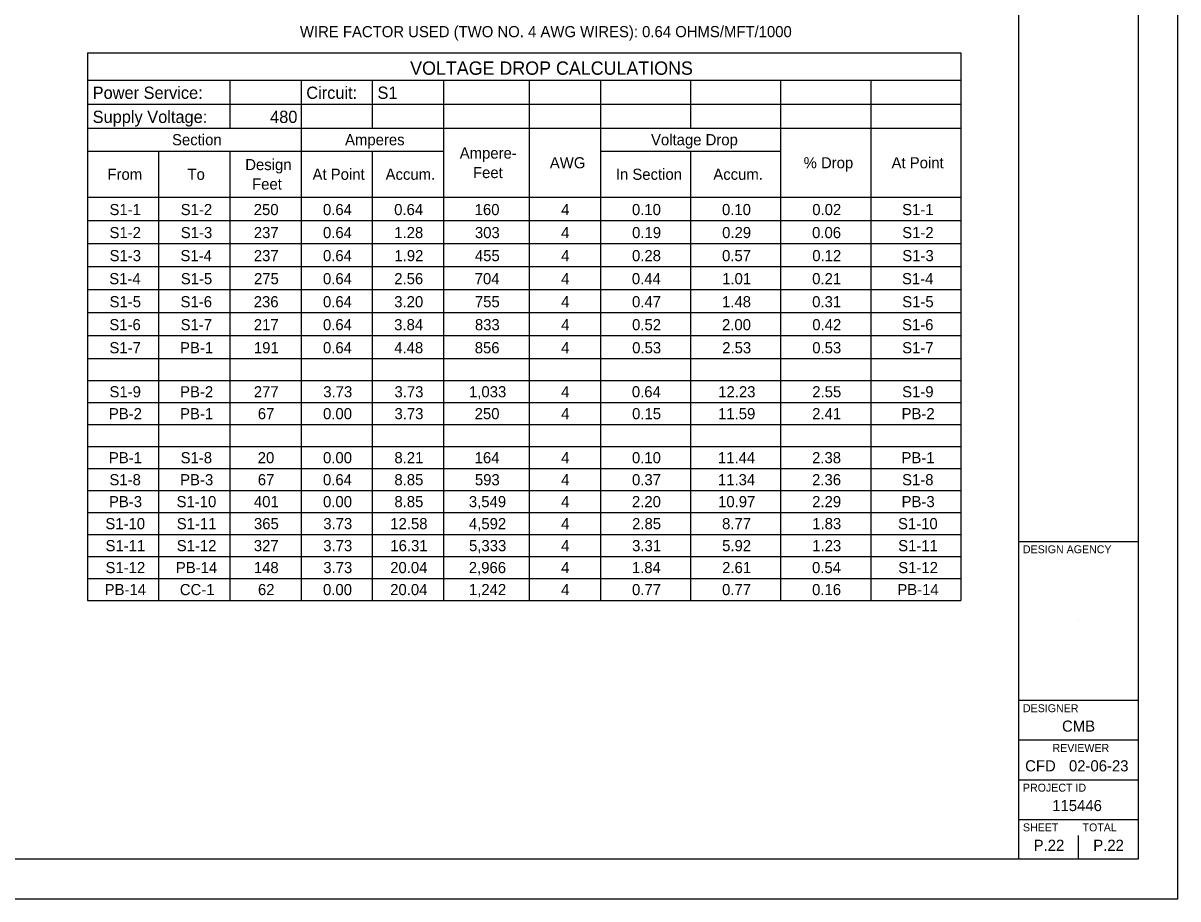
# Model space of a CAD drawing. Extents: x 0 to 34, y 0 to 22.
# Drawn here: x 19.47 to 34, y 0 to 11.02 of the extents above; entities that cross this region are included whole.
import ezdxf

# ---------------------------------------------------------------- set-up
doc = ezdxf.new("R2010")
doc.units = 0
for name, color, linetype in [('Default', 7, 'Continuous'), ('SH_Border', 7, 'Continuous'), ('SH_Cut_Line', 7, 'Continuous'), ('SH_Data', 7, 'Continuous'), ('SH_Text', 7, 'Continuous')]:
    doc.layers.add(name, color=color, linetype=linetype)

msp = doc.modelspace()

# ---------------------------------------------------------------- linework, layer by layer
at = {"layer": 'SH_Border'}
for p, q in [((32, 0.5), (32, 21.5)), ((32, 4.5), (33.5, 4.5)), ((32, 2.5), (33.5, 2.5)), ((32, 2), (33.5, 2)), ((32, 1.5), (33.5, 1.5)), ((32, 1), (33.5, 1))]:
    msp.add_line(p, q, dxfattribs=at)
msp.add_lwpolyline([(1.5, 21.5), (33.5, 21.5), (33.5, 0.5), (1.5, 0.5)], close=True, dxfattribs=at)
at = {"layer": 'SH_Cut_Line'}
msp.add_lwpolyline([(0, 0), (34, 0), (34, 22), (0, 22)], close=True, dxfattribs=at)
at = {"layer": 'SH_Data'}
for p, q in [((32.75, 3.5), (32.75, 3.5)), ((32.75, 0.5), (32.75, 0.8)), ((32.375, 0.675), (32.375, 0.675))]:
    msp.add_line(p, q, dxfattribs=at)
at = {"layer": 'SH_Text'}
for p, q in [((20.278, 10.648), (22.966, 10.648)), ((20.278, 10.648), (20.278, 9.7)), ((22.966, 10.648), (23.862, 10.648)), ((23.862, 10.648), (24.758, 10.648)), ((24.758, 10.648), (27.868, 10.648)), ((27.868, 10.648), (31.267, 10.648)), ((31.267, 10.648), (31.267, 9.7)), ((20.278, 10.306), (22.966, 10.306)), ((22.07, 10.306), (22.07, 9.7)), ((22.966, 10.306), (23.862, 10.306)), ((22.966, 10.306), (22.966, 9.7)), ((23.862, 10.306), (24.758, 10.306)), ((23.862, 10.306), (23.862, 9.7)), ((24.758, 10.306), (27.868, 10.306)), ((24.758, 10.306), (24.758, 9.7)), ((25.838, 10.306), (25.838, 9.7)), ((26.734, 10.306), (26.734, 9.7)), ((27.868, 10.306), (31.267, 10.306)), ((27.868, 10.306), (27.868, 9.7)), ((29.001, 10.306), (29.001, 9.7)), ((30.134, 10.306), (30.134, 9.7)), ((20.278, 10.003), (22.966, 10.003)), ((22.966, 10.003), (23.862, 10.003)), ((23.862, 10.003), (24.758, 10.003)), ((24.758, 10.003), (27.868, 10.003)), ((27.868, 10.003), (31.267, 10.003)), ((20.278, 9.7), (22.966, 9.7)), ((20.278, 9.7), (20.278, 7.381)), ((22.966, 9.7), (23.862, 9.7)), ((22.966, 9.7), (22.966, 7.381)), ((23.862, 9.7), (24.758, 9.7)), ((24.758, 9.7), (27.868, 9.7)), ((24.758, 9.7), (24.758, 7.381)), ((25.838, 9.7), (25.838, 7.381)), ((26.734, 9.7), (26.734, 7.381)), ((27.868, 9.7), (31.267, 9.7)), ((29.001, 9.7), (29.001, 7.381)), ((30.134, 9.7), (30.134, 7.381)), ((31.267, 9.7), (31.267, 7.381)), ((20.278, 9.41), (22.966, 9.41)), ((21.174, 9.41), (21.174, 7.381)), ((22.07, 9.41), (22.07, 7.381)), ((22.966, 9.41), (23.862, 9.41)), ((23.862, 9.41), (24.758, 9.41)), ((23.862, 9.41), (23.862, 7.381)), ((26.734, 9.41), (27.868, 9.41)), ((27.868, 9.41), (29.001, 9.41)), ((27.868, 9.41), (27.868, 7.381)), ((20.278, 8.83), (22.966, 8.83)), ((22.966, 8.83), (23.862, 8.83)), ((23.862, 8.83), (24.758, 8.83)), ((24.758, 8.83), (27.868, 8.83)), ((27.868, 8.83), (31.267, 8.83)), ((20.278, 8.54), (22.966, 8.54)), ((22.966, 8.54), (23.862, 8.54)), ((23.862, 8.54), (24.758, 8.54)), ((24.758, 8.54), (27.868, 8.54)), ((27.868, 8.54), (31.267, 8.54)), ((20.278, 8.25), (22.966, 8.25)), ((22.966, 8.25), (23.862, 8.25)), ((23.862, 8.25), (24.758, 8.25)), ((24.758, 8.25), (27.868, 8.25)), ((27.868, 8.25), (31.267, 8.25)), ((20.278, 7.96), (22.966, 7.96)), ((22.966, 7.96), (23.862, 7.96)), ((23.862, 7.96), (24.758, 7.96)), ((24.758, 7.96), (27.868, 7.96)), ((27.868, 7.96), (31.267, 7.96)), ((20.278, 7.67), (22.966, 7.67)), ((22.966, 7.67), (23.862, 7.67)), ((23.862, 7.67), (24.758, 7.67)), ((24.758, 7.67), (27.868, 7.67)), ((27.868, 7.67), (31.267, 7.67)), ((20.278, 7.381), (22.966, 7.381)), ((20.278, 7.381), (20.278, 7.091)), ((21.174, 7.381), (21.174, 7.091)), ((22.07, 7.381), (22.07, 7.091)), ((22.966, 7.381), (23.862, 7.381)), ((22.966, 7.381), (22.966, 7.091)), ((23.862, 7.381), (24.758, 7.381)), ((23.862, 7.381), (23.862, 7.091)), ((24.758, 7.381), (27.868, 7.381)), ((24.758, 7.381), (24.758, 7.091)), ((25.838, 7.381), (25.838, 7.091)), ((26.734, 7.381), (26.734, 7.091)), ((27.868, 7.381), (31.267, 7.381)), ((27.868, 7.381), (27.868, 7.091)), ((29.001, 7.381), (29.001, 7.091)), ((30.134, 7.381), (30.134, 7.091)), ((31.267, 7.381), (31.267, 7.091)), ((20.278, 7.091), (22.966, 7.091)), ((20.278, 7.091), (20.278, 4.864)), ((21.174, 7.091), (21.174, 4.864)), ((22.07, 7.091), (22.07, 4.864)), ((22.966, 7.091), (23.862, 7.091)), ((22.966, 7.091), (22.966, 4.864)), ((23.862, 7.091), (24.758, 7.091)), ((23.862, 7.091), (23.862, 4.864)), ((24.758, 7.091), (27.868, 7.091)), ((24.758, 7.091), (24.758, 4.864)), ((25.838, 7.091), (25.838, 4.864)), ((26.734, 7.091), (26.734, 4.864)), ((27.868, 7.091), (31.267, 7.091)), ((27.868, 7.091), (27.868, 4.864)), ((29.001, 7.091), (29.001, 4.864)), ((30.134, 7.091), (30.134, 4.864)), ((31.267, 7.091), (31.267, 4.864)), ((20.278, 6.801), (22.966, 6.801)), ((22.966, 6.801), (23.862, 6.801)), ((23.862, 6.801), (24.758, 6.801)), ((24.758, 6.801), (27.868, 6.801)), ((27.868, 6.801), (31.267, 6.801)), ((20.278, 6.524), (22.966, 6.524)), ((22.966, 6.524), (23.862, 6.524)), ((23.862, 6.524), (24.758, 6.524)), ((24.758, 6.524), (27.868, 6.524)), ((27.868, 6.524), (31.267, 6.524)), ((20.278, 6.247), (22.966, 6.247)), ((22.966, 6.247), (23.862, 6.247)), ((23.862, 6.247), (24.758, 6.247)), ((24.758, 6.247), (27.868, 6.247)), ((27.868, 6.247), (31.267, 6.247)), ((20.278, 5.971), (22.966, 5.971)), ((22.966, 5.971), (23.862, 5.971)), ((23.862, 5.971), (24.758, 5.971)), ((24.758, 5.971), (27.868, 5.971)), ((27.868, 5.971), (31.267, 5.971)), ((20.278, 5.694), (22.966, 5.694)), ((22.966, 5.694), (23.862, 5.694)), ((23.862, 5.694), (24.758, 5.694)), ((24.758, 5.694), (27.868, 5.694)), ((27.868, 5.694), (31.267, 5.694)), ((20.278, 5.417), (22.966, 5.417)), ((22.966, 5.417), (23.862, 5.417)), ((23.862, 5.417), (24.758, 5.417)), ((24.758, 5.417), (27.868, 5.417)), ((27.868, 5.417), (31.267, 5.417)), ((20.278, 5.141), (22.966, 5.141)), ((22.966, 5.141), (23.862, 5.141)), ((23.862, 5.141), (24.758, 5.141)), ((24.758, 5.141), (27.868, 5.141)), ((27.868, 5.141), (31.267, 5.141)), ((20.278, 4.864), (22.966, 4.864)), ((20.278, 4.864), (20.278, 4.587)), ((21.174, 4.864), (21.174, 4.587)), ((22.07, 4.864), (22.07, 4.587)), ((22.966, 4.864), (23.862, 4.864)), ((22.966, 4.864), (22.966, 4.587)), ((23.862, 4.864), (24.758, 4.864)), ((23.862, 4.864), (23.862, 4.587)), ((24.758, 4.864), (27.868, 4.864)), ((24.758, 4.864), (24.758, 4.587)), ((25.838, 4.864), (25.838, 4.587)), ((26.734, 4.864), (26.734, 4.587)), ((27.868, 4.864), (31.267, 4.864)), ((27.868, 4.864), (27.868, 4.587)), ((29.001, 4.864), (29.001, 4.587)), ((30.134, 4.864), (30.134, 4.587)), ((31.267, 4.864), (31.267, 4.587)), ((20.278, 4.587), (22.966, 4.587)), ((20.278, 4.587), (20.278, 4.31)), ((21.174, 4.587), (21.174, 4.31)), ((22.07, 4.587), (22.07, 4.31)), ((22.966, 4.587), (23.862, 4.587)), ((22.966, 4.587), (22.966, 4.31)), ((23.862, 4.587), (24.758, 4.587)), ((23.862, 4.587), (23.862, 4.31)), ((24.758, 4.587), (27.868, 4.587)), ((24.758, 4.587), (24.758, 4.31)), ((25.838, 4.587), (25.838, 4.31)), ((26.734, 4.587), (26.734, 4.31)), ((27.868, 4.587), (31.267, 4.587)), ((27.868, 4.587), (27.868, 4.31)), ((29.001, 4.587), (29.001, 4.31)), ((30.134, 4.587), (30.134, 4.31)), ((31.267, 4.587), (31.267, 4.31)), ((20.278, 4.31), (22.966, 4.31)), ((20.278, 4.31), (20.278, 4.034)), ((21.174, 4.31), (21.174, 4.034)), ((22.07, 4.31), (22.07, 4.034)), ((22.966, 4.31), (23.862, 4.31)), ((22.966, 4.31), (22.966, 4.034)), ((23.862, 4.31), (24.758, 4.31)), ((23.862, 4.31), (23.862, 4.034)), ((24.758, 4.31), (27.868, 4.31)), ((24.758, 4.31), (24.758, 4.034)), ((25.838, 4.31), (25.838, 4.034)), ((26.734, 4.31), (26.734, 4.034)), ((27.868, 4.31), (31.267, 4.31)), ((27.868, 4.31), (27.868, 4.034)), ((29.001, 4.31), (29.001, 4.034)), ((30.134, 4.31), (30.134, 4.034)), ((31.267, 4.31), (31.267, 4.034)), ((20.278, 4.034), (22.966, 4.034)), ((20.278, 4.034), (20.278, 3.757)), ((21.174, 4.034), (21.174, 3.757)), ((22.07, 4.034), (22.07, 3.757)), ((22.966, 4.034), (23.862, 4.034)), ((22.966, 4.034), (22.966, 3.757)), ((23.862, 4.034), (24.758, 4.034)), ((23.862, 4.034), (23.862, 3.757)), ((24.758, 4.034), (27.868, 4.034)), ((24.758, 4.034), (24.758, 3.757)), ((25.838, 4.034), (25.838, 3.757)), ((26.734, 4.034), (26.734, 3.757)), ((27.868, 4.034), (31.267, 4.034)), ((27.868, 4.034), (27.868, 3.757)), ((29.001, 4.034), (29.001, 3.757)), ((30.134, 4.034), (30.134, 3.757)), ((31.267, 4.034), (31.267, 3.757)), ((20.278, 3.757), (22.966, 3.757)), ((22.966, 3.757), (23.862, 3.757)), ((23.862, 3.757), (24.758, 3.757)), ((24.758, 3.757), (27.868, 3.757)), ((27.868, 3.757), (31.267, 3.757))]:
    msp.add_line(p, q, dxfattribs=at)

# ---------------------------------------------------------------- texts
at = {"layer": 'Default'}
msp.add_text('WIRE FACTOR USED (TWO NO. 4 AWG WIRES): 0.64 OHMS/MFT/1000', height=0.14, dxfattribs=at).set_placement((22.952, 10.845))
at = {"layer": 'SH_Data'}
for s, height, p in [('DESIGN AGENCY', 0.1, (32.05, 4.35)), ('DESIGNER', 0.1, (32.05, 2.35)), ('CMB', 0.14, (32.542, 2.105)), ('REVIEWER', 0.1, (32.422, 1.85)), ('CFD', 0.14, (32.078, 1.605)), ('02-06-23', 0.14, (32.629, 1.605)), ('PROJECT ID', 0.1, (32.05, 1.35)), ('115446', 0.14, (32.419, 1.105)), ('SHEET', 0.1, (32.05, 0.85)), ('TOTAL', 0.1, (32.8, 0.85)), ('P.22', 0.14, (32.185, 0.605)), ('P.22', 0.14, (32.935, 0.605))]:
    msp.add_text(s, height=height, dxfattribs=at).set_placement(p)
at = {"layer": 'SH_Text'}
for s, height, p in [('VOLTAGE DROP CALCULATIONS', 0.168, (24.339, 10.372)), ('Power Service:', 0.154, (20.344, 10.069)), ('Circuit:', 0.154, (23.032, 10.069)), ('S1', 0.154, (23.928, 10.069)), ('Supply Voltage:', 0.154, (20.344, 9.766)), ('480', 0.154, (22.577, 9.766)), ('Section', 0.14, (21.343, 9.485)), ('Amperes', 0.14, (23.52, 9.485)), ('Voltage Drop', 0.14, (27.37, 9.485)), ('Ampere-', 0.14, (24.963, 9.317)), ('Design', 0.14, (22.264, 9.172)), ('AWG', 0.14, (26.097, 9.195)), ('% Drop', 0.14, (29.29, 9.195)), ('At Point', 0.14, (30.397, 9.195)), ('From', 0.14, (20.53, 9.05)), ('To', 0.14, (21.537, 9.05)), ('At Point', 0.14, (23.111, 9.05)), ('Accum.', 0.14, (24.03, 9.05)), ('Feet', 0.14, (25.13, 9.072)), ('In Section', 0.14, (26.927, 9.05)), ('Accum.', 0.14, (28.154, 9.05)), ('Feet', 0.14, (22.35, 8.927)), ('S1-1', 0.14, (20.556, 8.606)), ('S1-2', 0.14, (21.452, 8.606)), ('250', 0.14, (22.371, 8.606)), ('0.64', 0.14, (23.242, 8.606)), ('0.64', 0.14, (24.138, 8.606)), ('160', 0.14, (25.151, 8.606)), ('4', 0.14, (26.239, 8.606)), ('0.10', 0.14, (27.13, 8.606)), ('0.10', 0.14, (28.263, 8.606)), ('0.02', 0.14, (29.399, 8.606)), ('S1-1', 0.14, (30.53, 8.606)), ('S1-2', 0.14, (20.556, 8.316)), ('S1-3', 0.14, (21.453, 8.316)), ('237', 0.14, (22.372, 8.316)), ('0.64', 0.14, (23.242, 8.316)), ('1.28', 0.14, (24.139, 8.316)), ('303', 0.14, (25.154, 8.316)), ('4', 0.14, (26.239, 8.316)), ('0.19', 0.14, (27.132, 8.316)), ('0.29', 0.14, (28.265, 8.316)), ('0.06', 0.14, (29.397, 8.316)), ('S1-2', 0.14, (30.531, 8.316)), ('S1-3', 0.14, (20.557, 8.026)), ('S1-4', 0.14, (21.449, 8.026)), ('237', 0.14, (22.372, 8.026)), ('0.64', 0.14, (23.242, 8.026)), ('1.92', 0.14, (24.141, 8.026)), ('455', 0.14, (25.154, 8.026)), ('4', 0.14, (26.239, 8.026)), ('0.28', 0.14, (27.131, 8.026)), ('0.57', 0.14, (28.264, 8.026)), ('0.12', 0.14, (29.399, 8.026)), ('S1-3', 0.14, (30.532, 8.026)), ('S1-4', 0.14, (20.553, 7.736)), ('S1-5', 0.14, (21.453, 7.736)), ('275', 0.14, (22.374, 7.736)), ('0.64', 0.14, (23.242, 7.736)), ('2.56', 0.14, (24.139, 7.736)), ('704', 0.14, (25.151, 7.736)), ('4', 0.14, (26.239, 7.736)), ('0.44', 0.14, (27.129, 7.736)), ('1.01', 0.14, (28.265, 7.736)), ('0.21', 0.14, (29.398, 7.736)), ('S1-4', 0.14, (30.528, 7.736)), ('S1-5', 0.14, (20.557, 7.446)), ('S1-6', 0.14, (21.45, 7.446)), ('236', 0.14, (22.371, 7.446)), ('0.64', 0.14, (23.242, 7.446)), ('3.20', 0.14, (24.139, 7.446)), ('755', 0.14, (25.154, 7.446)), ('4', 0.14, (26.239, 7.446)), ('0.47', 0.14, (27.131, 7.446)), ('1.48', 0.14, (28.264, 7.446)), ('0.31', 0.14, (29.398, 7.446)), ('S1-5', 0.14, (30.531, 7.446)), ('S1-6', 0.14, (20.554, 7.157)), ('S1-7', 0.14, (21.451, 7.157)), ('217', 0.14, (22.372, 7.157)), ('0.64', 0.14, (23.242, 7.157)), ('3.84', 0.14, (24.138, 7.157)), ('833', 0.14, (25.154, 7.157)), ('4', 0.14, (26.239, 7.157)), ('0.52', 0.14, (27.132, 7.157)), ('2.00', 0.14, (28.263, 7.157)), ('0.42', 0.14, (29.399, 7.157)), ('S1-6', 0.14, (30.529, 7.157)), ('S1-7', 0.14, (20.555, 6.867)), ('PB-1', 0.14, (21.444, 6.867)), ('191', 0.14, (22.373, 6.867)), ('0.64', 0.14, (23.242, 6.867)), ('4.48', 0.14, (24.139, 6.867)), ('856', 0.14, (25.152, 6.867)), ('4', 0.14, (26.239, 6.867)), ('0.53', 0.14, (27.133, 6.867)), ('2.53', 0.14, (28.266, 6.867)), ('0.53', 0.14, (29.399, 6.867)), ('S1-7', 0.14, (30.53, 6.867)), ('S1-9', 0.14, (20.556, 6.313)), ('PB-2', 0.14, (21.444, 6.313)), ('277', 0.14, (22.372, 6.313)), ('3.73', 0.14, (23.246, 6.313)), ('3.73', 0.14, (24.142, 6.313)), ('1,033', 0.14, (25.08, 6.313)), ('4', 0.14, (26.239, 6.313)), ('0.64', 0.14, (27.129, 6.313)), ('12.23', 0.14, (28.216, 6.313)), ('2.55', 0.14, (29.399, 6.313)), ('S1-9', 0.14, (30.53, 6.313)), ('PB-2', 0.14, (20.548, 6.037)), ('PB-1', 0.14, (21.444, 6.037)), ('67', 0.14, (22.422, 6.037)), ('0.00', 0.14, (23.243, 6.037)), ('3.73', 0.14, (24.142, 6.037)), ('250', 0.14, (25.151, 6.037)), ('4', 0.14, (26.239, 6.037)), ('0.15', 0.14, (27.132, 6.037)), ('11.59', 0.14, (28.214, 6.037)), ('2.41', 0.14, (29.398, 6.037)), ('PB-2', 0.14, (30.523, 6.037)), ('PB-1', 0.14, (20.548, 5.483)), ('S1-8', 0.14, (21.451, 5.483)), ('20', 0.14, (22.421, 5.483)), ('0.00', 0.14, (23.243, 5.483)), ('8.21', 0.14, (24.141, 5.483)), ('164', 0.14, (25.151, 5.483)), ('4', 0.14, (26.239, 5.483)), ('0.10', 0.14, (27.13, 5.483)), ('11.44', 0.14, (28.212, 5.483)), ('2.38', 0.14, (29.397, 5.483)), ('PB-1', 0.14, (30.522, 5.483)), ('S1-8', 0.14, (20.555, 5.206)), ('PB-3', 0.14, (21.445, 5.206)), ('67', 0.14, (22.422, 5.206)), ('0.64', 0.14, (23.242, 5.206)), ('8.85', 0.14, (24.141, 5.206)), ('593', 0.14, (25.154, 5.206)), ('4', 0.14, (26.239, 5.206)), ('0.37', 0.14, (27.131, 5.206)), ('11.34', 0.14, (28.212, 5.206)), ('2.36', 0.14, (29.397, 5.206)), ('S1-8', 0.14, (30.529, 5.206)), ('PB-3', 0.14, (20.549, 4.93)), ('S1-10', 0.14, (21.4, 4.93)), ('401', 0.14, (22.373, 4.93)), ('0.00', 0.14, (23.243, 4.93)), ('8.85', 0.14, (24.141, 4.93)), ('3,549', 0.14, (25.078, 4.93)), ('4', 0.14, (26.239, 4.93)), ('2.20', 0.14, (27.13, 4.93)), ('10.97', 0.14, (28.214, 4.93)), ('2.29', 0.14, (29.398, 4.93)), ('PB-3', 0.14, (30.523, 4.93)), ('S1-10', 0.14, (20.504, 4.653)), ('S1-11', 0.14, (21.402, 4.653)), ('365', 0.14, (22.374, 4.653)), ('3.73', 0.14, (23.246, 4.653)), ('12.58', 0.14, (24.089, 4.653)), ('4,592', 0.14, (25.079, 4.653)), ('4', 0.14, (26.239, 4.653)), ('2.85', 0.14, (27.132, 4.653)), ('8.77', 0.14, (28.264, 4.653)), ('1.83', 0.14, (29.399, 4.653)), ('S1-10', 0.14, (30.478, 4.653)), ('S1-11', 0.14, (20.506, 4.376)), ('S1-12', 0.14, (21.402, 4.376)), ('327', 0.14, (22.372, 4.376)), ('3.73', 0.14, (23.246, 4.376)), ('16.31', 0.14, (24.09, 4.376)), ('5,333', 0.14, (25.08, 4.376)), ('4', 0.14, (26.239, 4.376)), ('3.31', 0.14, (27.132, 4.376)), ('5.92', 0.14, (28.265, 4.376)), ('1.23', 0.14, (29.399, 4.376)), ('S1-11', 0.14, (30.48, 4.376)), ('S1-12', 0.14, (20.506, 4.1)), ('PB-14', 0.14, (21.391, 4.1)), ('148', 0.14, (22.372, 4.1)), ('3.73', 0.14, (23.246, 4.1)), ('20.04', 0.14, (24.088, 4.1)), ('2,966', 0.14, (25.077, 4.1)), ('4', 0.14, (26.239, 4.1)), ('1.84', 0.14, (27.129, 4.1)), ('2.61', 0.14, (28.265, 4.1)), ('0.54', 0.14, (29.396, 4.1)), ('S1-12', 0.14, (30.481, 4.1)), ('PB-14', 0.14, (20.495, 3.823)), ('CC-1', 0.14, (21.441, 3.823)), ('62', 0.14, (22.424, 3.823)), ('0.00', 0.14, (23.243, 3.823)), ('20.04', 0.14, (24.088, 3.823)), ('1,242', 0.14, (25.079, 3.823)), ('4', 0.14, (26.239, 3.823)), ('0.77', 0.14, (27.131, 3.823)), ('0.77', 0.14, (28.264, 3.823)), ('0.16', 0.14, (29.397, 3.823)), ('PB-14', 0.14, (30.469, 3.823))]:
    msp.add_text(s, height=height, dxfattribs=at).set_placement(p)

doc.saveas('drawing.dxf')
